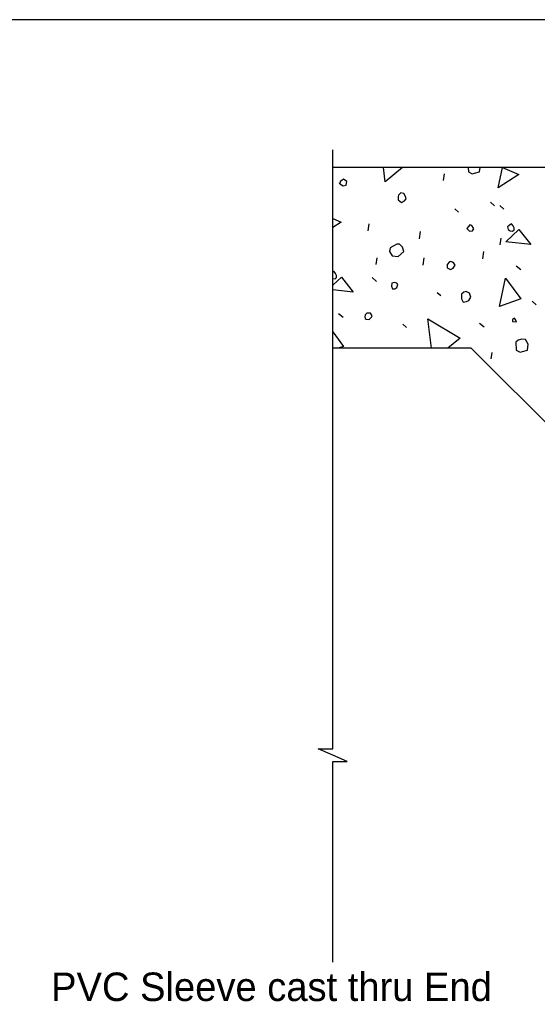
# Model space of a CAD drawing. Extents: x 112544 to 112597.1, y 111084 to 111107.1.
# Drawn here: x 112563.35 to 112566.09, y 111100.15 to 111105.36 of the extents above; entities that cross this region are included whole.
import ezdxf

# ---------------------------------------------------------------- set-up
doc = ezdxf.new("R2010")
doc.units = 0
for name, color, linetype in [('ActivePts-ConstElements', 7, 'Continuous'), ('Dimension', 7, 'Continuous'), ('Miscellaneous', 7, 'Continuous'), ('SupstrConc', 7, 'Continuous')]:
    doc.layers.add(name, color=color, linetype=linetype)

msp = doc.modelspace()

# ---------------------------------------------------------------- linework, layer by layer
at = {"layer": 'ActivePts-ConstElements'}
msp.add_lwpolyline([(112543.9918, 111085.9039), (112574.7797, 111085.9039), (112574.7797, 111105.3634), (112543.9918, 111105.3634)], close=True, dxfattribs=at)
at = {"layer": 'Dimension'}
msp.add_lwpolyline([(112565.0089, 111100.364), (112565.0089, 111101.4284), (112565.0864, 111101.4284), (112565.0089, 111101.4621), (112564.9314, 111101.4959), (112565.0089, 111101.4959), (112565.0089, 111104.6722)], dxfattribs=at)
at = {"layer": 'Miscellaneous'}
for p, q in [((112565.5958, 111104.5101), (112565.6018, 111104.5453)), ((112565.6565, 111104.3607), (112565.6768, 111104.3429)), ((112565.8463, 111104.396), (112565.8673, 111104.3758)), ((112565.8951, 111104.3781), (112565.9161, 111104.3578)), ((112565.1964, 111104.2426), (112565.2018, 111104.2803)), ((112565.4688, 111104.2017), (112565.4742, 111104.2394)), ((112565.8968, 111104.1689), (112565.9029, 111104.2041)), ((112565.2388, 111104.065), (112565.2449, 111104.1003)), ((112565.4881, 111104.0619), (112565.4935, 111104.0996)), ((112565.8053, 111104.0952), (112565.8107, 111104.1329)), ((112565.9812, 111104.0569), (112566.007, 111104.0379)), ((112565.2187, 111103.9949), (112565.2421, 111103.9753)), ((112565.5633, 111103.9164), (112565.583, 111103.901)), ((112566.0674, 111103.8703), (112566.0884, 111103.8501)), ((112565.0394, 111103.8045), (112565.0652, 111103.7856)), ((112565.3806, 111103.7484), (112565.4009, 111103.7306)), ((112565.788, 111103.7541), (112565.8114, 111103.7344)), ((112565.8494, 111103.5635), (112565.8555, 111103.5987))]:
    msp.add_line(p, q, dxfattribs=at)
for points in [[(112565.2872, 111104.5025), (112565.2776, 111104.5786)], [(112565.3795, 111104.5786), (112565.2872, 111104.5025)], [(112565.7277, 111104.5786), (112565.7284, 111104.556), (112565.7492, 111104.546), (112565.7613, 111104.5492), (112565.7878, 111104.5564), (112565.7908, 111104.5786)], [(112565.8857, 111104.4713), (112565.9087, 111104.5784), (112565.9961, 111104.5423), (112565.8857, 111104.4713)], [(112565.0466, 111104.4923), (112565.065, 111104.4817), (112565.0795, 111104.4856), (112565.0846, 111104.5051), (112565.0656, 111104.5181), (112565.0572, 111104.5107), (112565.0482, 111104.5057), (112565.0466, 111104.4923), (112565.0453, 111104.4972)], [(112565.357, 111104.4254), (112565.3567, 111104.4072), (112565.3733, 111104.3935), (112565.389, 111104.4029), (112565.3991, 111104.4134), (112565.3959, 111104.4255), (112565.3865, 111104.4411), (112565.3701, 111104.4444), (112565.3575, 111104.4333), (112565.357, 111104.4254)], [(112565.0089, 111104.3087), (112565.0543, 111104.2899), (112565.0089, 111104.2607)], [(112565.7207, 111104.2563), (112565.7349, 111104.2419), (112565.75, 111104.2434), (112565.7578, 111104.2532), (112565.7565, 111104.2581), (112565.7477, 111104.2713), (112565.7361, 111104.2759), (112565.7284, 111104.2661), (112565.7207, 111104.2563)], [(112565.9263, 111104.1845), (112565.9967, 111104.25), (112566.0593, 111104.171), (112565.9263, 111104.1845)], [(112565.9397, 111104.2502), (112565.9496, 111104.2425), (112565.9629, 111104.2409), (112565.9713, 111104.2484), (112565.9711, 111104.2587), (112565.9655, 111104.2701), (112565.9574, 111104.2809), (112565.9442, 111104.2722), (112565.9359, 111104.2647), (112565.9397, 111104.2502)], [(112565.311, 111104.1335), (112565.3247, 111104.1113), (112565.3569, 111104.107), (112565.3862, 111104.133), (112565.3797, 111104.1571), (112565.3625, 111104.1732), (112565.3498, 111104.1724), (112565.3293, 111104.1617), (112565.3137, 111104.1524), (112565.311, 111104.1335)], [(112565.6166, 111104.0653), (112565.6163, 111104.0471), (112565.634, 111104.0389), (112565.6479, 111104.0452), (112565.6591, 111104.0612), (112565.651, 111104.072), (112565.6443, 111104.0779), (112565.6333, 111104.0801), (112565.6285, 111104.0789), (112565.6166, 111104.0653)], [(112565.0089, 111103.9901), (112565.0212, 111103.9886), (112565.0295, 111103.996), (112565.0293, 111104.0063), (112565.0237, 111104.0177), (112565.0156, 111104.0285), (112565.0089, 111104.0241)], [(112565.0089, 111103.9548), (112565.055, 111103.9976), (112565.1175, 111103.9186), (112565.0089, 111103.9297)], [(112565.8938, 111103.842), (112565.9259, 111103.9929), (112566.0072, 111103.8827), (112565.8938, 111103.842)], [(112565.3214, 111103.95), (112565.3253, 111103.9355), (112565.338, 111103.9363), (112565.3494, 111103.942), (112565.3552, 111103.959), (112565.3484, 111103.965), (112565.3368, 111103.9696), (112565.3223, 111103.9658), (112565.3214, 111103.95)], [(112565.6926, 111103.9071), (112565.6912, 111103.8834), (112565.7012, 111103.8654), (112565.7188, 111103.8675), (112565.7302, 111103.8732), (112565.7408, 111103.8915), (112565.735, 111103.9133), (112565.7172, 111103.9215), (112565.7052, 111103.9182), (112565.6926, 111103.9071)], [(112565.1812, 111103.7778), (112565.1873, 111103.7743), (112565.2031, 111103.7733), (112565.2156, 111103.7845), (112565.2185, 111103.793), (112565.2098, 111103.8062), (112565.1892, 111103.8058), (112565.1808, 111103.7984), (112565.1786, 111103.7875), (112565.1812, 111103.7778)], [(112565.5327, 111103.6203), (112565.5129, 111103.7761), (112565.685, 111103.6747), (112565.619, 111103.6203)], [(112565.9619, 111103.7618), (112565.9832, 111103.7598), (112565.9806, 111103.7694), (112565.9725, 111103.7802), (112565.9617, 111103.7721), (112565.9619, 111103.7618)], [(112565.0089, 111103.707), (112565.0654, 111103.6303), (112565.0374, 111103.6203)], [(112565.9807, 111103.653), (112565.982, 111103.6094), (112566.0028, 111103.5994), (112566.0149, 111103.6026), (112566.0415, 111103.6098), (112566.0458, 111103.642), (112566.0314, 111103.6666), (112566.0126, 111103.6693), (112565.9933, 111103.6641), (112565.9807, 111103.653)]]:
    msp.add_lwpolyline(points, dxfattribs=at)
at = {"layer": 'SupstrConc'}
for p, q in [((112569.7858, 111104.5786), (112565.0089, 111104.5786)), ((112565.7441, 111103.6203), (112565.0089, 111103.6203)), ((112566.6191, 111102.7453), (112565.7441, 111103.6203))]:
    msp.add_line(p, q, dxfattribs=at)

# ---------------------------------------------------------------- texts
at = {"layer": 'Dimension'}
msp.add_text('PVC Sleeve cast thru End ', height=0.1512, dxfattribs=at).set_placement((112563.5155, 111100.1574))

doc.saveas('drawing.dxf')
